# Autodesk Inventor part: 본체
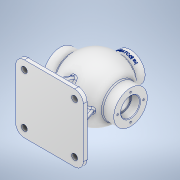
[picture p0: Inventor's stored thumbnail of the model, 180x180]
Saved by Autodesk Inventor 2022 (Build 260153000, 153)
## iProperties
Created: 2024-04
Part Number: 본체
Material: 알루미늄 6061
Document SubType Name: Modeling
Designer: user
Density: 2.7 g/cm^3
Appearance: 알루미늄 - 평지
Mass: 1528.11 g
Surface Area: 1173.66 cm^2
Volume: 565.967 cm^3
Author: user
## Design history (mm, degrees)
sketch "스케치1"
  geometry: L1 (-91, 0)-(91, 0) reference; L2 (0, -10.8)-(0, 64.8) reference; L3 (-44.215, 31)-(-65, 31); L4 (44.215, 31)-(65, 31); L5 (-65, 31)-(-65, 0); L6 (65, 31)-(65, 0); L7 (-44, 0)-(-65, 0); L8 (44, 0)-(65, 0); A1 r 54 centre (0, 0) between (44.215, 31) and (-44.215, 31); A2 r 44 centre (0, 0) between (44, 0) and (-44, 0); 1 further point
  constraints: 12 end point, 4 point on circle, 4 point on line, 3 collinear, 2 centre point, 2 coincident, 2 horizontal, 2 perpendicular
  dimensions: "d0" = 54 radius of A1; "d1" = 130 distance of L4.end L3.end; "d2" = 62 diameter of L3.end L1; "d3" = 62 diameter of L4.end L1; "d4" = 44 radius of A2
revolve "회전1" sketch "스케치1" stored, may be unused: angle "d5" = 90 deg
sketch "스케치2"
  geometry: C1 r 17.5 at (0, 0); 1 further point
  constraints: 1 centre point, 1 coincident
  dimensions: "d6" = 35 diameter of C1
extrude "돌출1" cut sketch "스케치2" distance "d7" = 16; taper "d8" = 0 deg
sketch "스케치3"
  geometry: C1 r 15 at (0, 0); 1 further point
  constraints: 1 centre point, 1 coincident
  dimensions: "d9" = 30 diameter of C1
extrude "돌출2" cut sketch "스케치3" extent not by distance; stored distance "d10" = 0; taper "d11" = 0 deg
node "작업 평면1"
sketch "스케치4"
  geometry: C1 r 27 at (0, 0); 1 further point
  constraints: 1 centre point, 1 coincident
  dimensions: "d14" = 54 diameter of C1
extrude "돌출3" join sketch "스케치4" stored distance "d15" = 10; taper "d16" = 0 deg
sketch "스케치5"
  geometry: C1 r 13 at (0, 0); 1 further point
  constraints: 1 centre point, 1 coincident
  dimensions: "d17" = 26 diameter of C1
extrude "돌출4" cut sketch "스케치5" stored distance "d18" = 10; taper "d19" = 0 deg
node "작업 평면2"
sketch "스케치6"
  geometry: L1 (62.5, -62.5)-(-62.5, -62.5); L2 (-62.5, -62.5)-(-62.5, 62.5); L3 (-62.5, 62.5)-(62.5, 62.5); L4 (62.5, 62.5)-(62.5, -62.5); L5 (62.5, -62.5)-(-62.5, 62.5); L6 (-62.5, -62.5)-(62.5, 62.5); 1 further point
  constraints: 12 end point, 2 midpoint, 2 parallel, 1 horizontal, 1 perpendicular
  dimensions: "d21" = 125 distance of L2.end L3.end; "d22" = 125 distance of L1.end L2.end
extrude "돌출5" join sketch "스케치6" distance "d23" = 10; taper "d24" = 0 deg
sketch "스케치7"
  geometry: L1 (-91, 85)-(91, 85) reference; L2 (-62.5, 75)-(62.5, 75) reference; L3 (50.5, 75)-(35.692, 34.314); L4 (62.5, 85)-(62.5, 75) reference; L5 (35.692, 34.314)-(0, 52.046); L6 (0, 52.046)-(0, 75); L7 (50.5, 75)-(0, 75); A1 r 54 centre (0, 0) between (-44.215, -31) and (-44.215, 31) reference; 1 further point
  constraints: 8 end point, 1 collinear, 1 midpoint, 1 point on line
  dimensions: "d25" = 85 distance from line of L1 point (0, 0) (derived); "d26" = 12 distance from line of L4 L3.start; "d27" = 20 deg angle of L4 L3
extrude "돌출6" join sketch "스케치7" stored distance "d28" = 8; taper "d29" = 0 deg
node "작업 평면3"
sketch "스케치8"
  geometry: L1 (62.5, 75)-(-62.5, 75) reference; L2 (-50.5, 75)-(-36.752, 37.227); L3 (-62.5, 85)-(-62.5, 75) reference; L4 (-36.752, 37.227)-(0, 52.688); L5 (0, 52.688)-(0, 75); L6 (-50.5, 75)-(0, 75); 1 further point
  constraints: 8 end point, 1 collinear, 1 midpoint, 1 point on line
  dimensions: "d31" = 12 distance from line of L3 L2.start; "d32" = 20 deg angle of L3 L2
extrude "돌출7" join sketch "스케치8" stored distance "d33" = 8; taper "d34" = 0 deg
fillet "모깎기2" dims "d35" = 16
fillet "모깎기3" dims "d36" = 3
fillet "모깎기4" dims "d37" = 3
fillet "모깎기5" dims "d38" = 3
sketch "스케치9"
  geometry: C1 r 5.5 at (46.5, -46.5); A1 r 16 centre (46.5, -46.5) between (46.5, -62.5) and (62.5, -46.5) reference; 1 further point
  constraints: 1 centre point, 1 coincident
  dimensions: "d39" = 11 diameter of C1
extrude "돌출8" cut sketch "스케치9" extent not by distance; stored distance "d40" = 0; taper "d41" = 0 deg
sketch "스케치10" dims "d42" = 48
  geometry: 3 further points
  constraints: 1 coincident, 1 horizontal alignment, 2 other
hole "구멍1" sketch "스케치10" at (-24, 0) diameter "d43" = 3.242; stored, may be unused: countersink angle "d47" = 90 deg, drill point angle "d49" = 118 deg; dims "d44" = 12, "d45" = 12, "d46" = 5, "d48" = 15
sketch "스케치11" dims "d53" = 40
  geometry: 3 further points
  constraints: 1 coincident, 1 vertical alignment, 2 other
hole "구멍2" sketch "스케치11" at (0, -20) diameter "d54" = 3.242; stored, may be unused: countersink angle "d58" = 90 deg, drill point angle "d60" = 118 deg; dims "d55" = 9, "d56" = 4, "d57" = 2, "d59" = 11
chamfer "모따기1" distance "d64" = 1; stored, may be unused: second distance "d65" = 2, angle "d66" = 45 deg
node "작업 평면4"
sketch "스케치12"
  geometry: L1 (27, -65)-(-27, -65) reference; 2 further points
  constraints: 1 vertical alignment, 1 other
  dimensions: "d68" = 9 distance from line of L1 point (0, -56)
feature "엠보싱1" sketch "스케치12" dims "d9" = 30, "d69" = 0.5, "d70" = 0
fillet "모깎기6" dims "d71" = 0.6
node "솔리드1"
mirror "미러1"
mirror "미러2"
mirror "미러3"
mirror "미러4"
mirror "미러5"
pattern_circular "원형 패턴1" dims angle "d51" = 360 deg
mirror "미러6"
pattern_circular "원형 패턴2" dims angle "d62" = 360 deg
feature "A9D066F2-1C7D-4E18-AEED-F7BC21143FA4" dims "d43" = 3.242, "d44" = 12, "d45" = 12, "d46" = 5, "d47" = 90 deg, "d48" = 15, "d49" = 118 deg
other parameters: "d13" = -65, "d20" = 85, "d30" = 0, "d67" = 84.5
